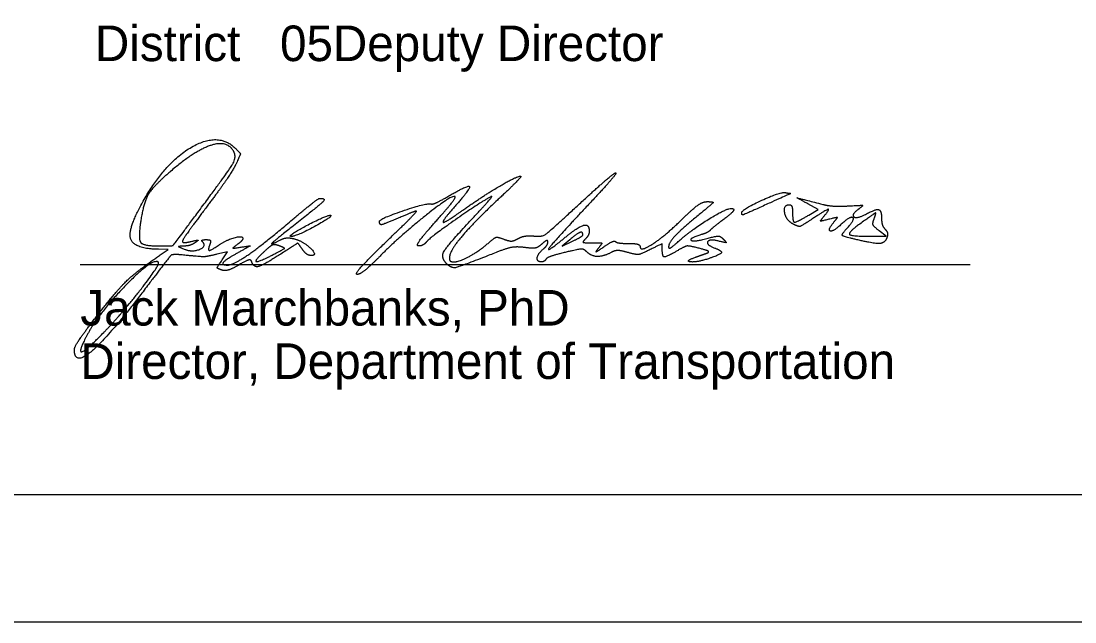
# Model space of a CAD drawing. Extents: x 0 to 40.4, y 0 to 22.
# Drawn here: x 25.71 to 29.855, y 0 to 2.364 of the extents above; entities that cross this region are included whole.
import ezdxf

# ---------------------------------------------------------------- set-up
doc = ezdxf.new("R2010")
doc.units = 0
for name, color, linetype in [('SH_Border', 7, 'Continuous'), ('SH_Cut_Line', 7, 'Continuous'), ('SH_Data', 7, 'Continuous'), ('SH_Text', 7, 'Continuous')]:
    doc.layers.add(name, color=color, linetype=linetype)

msp = doc.modelspace()

# ---------------------------------------------------------------- linework, layer by layer
at = {"layer": 'SH_Border'}
msp.add_lwpolyline([(2, 21.5), (33.5, 21.5), (33.5, 0.5), (2, 0.5)], close=True, dxfattribs=at)
at = {"layer": 'SH_Cut_Line'}
msp.add_lwpolyline([(0, 0), (34, 0), (34, 22), (0, 22)], close=True, dxfattribs=at)
at = {"layer": 'SH_Data'}
msp.add_line((25.9426, 1.4059), (29.4426, 1.4059), dxfattribs=at)
at = {"layer": 'SH_Text'}
for p, q in [((26.4049, 1.6109), (26.4049, 1.6109)), ((28.5442, 1.6101), (28.5442, 1.6101)), ((26.7703, 1.5211), (26.7703, 1.5211)), ((27.9192, 1.5231), (27.9192, 1.5231)), ((28.9967, 1.5038), (28.9967, 1.5038)), ((26.7255, 1.4794), (26.7255, 1.4794)), ((27.1421, 1.492), (27.1421, 1.492))]:
    msp.add_line(p, q, dxfattribs=at)
for points in [[(28.808, 1.6005), (28.8444, 1.622), (28.8037, 1.645)], [(29.0567, 1.517), (29.113, 1.5171), (29.0842, 1.5392)], [(27.8675, 1.5034), (27.838, 1.4778), (27.8786, 1.4975)], [(26.2573, 1.444), (26.288, 1.4652), (26.2501, 1.4659)], [(26.5002, 1.4241), (26.5214, 1.4565), (26.4797, 1.4464)]]:
    msp.add_lwpolyline(points, dxfattribs=at)
for points in [[(26.1936, 1.6617), (26.2799, 1.8121), (26.488, 1.9281), (26.5537, 1.8624)], [(26.5447, 1.8533), (26.5187, 1.8953), (26.3926, 1.8541), (26.2973, 1.7725)], [(26.4049, 1.6109), (26.5263, 1.7744), (26.5587, 1.8306), (26.5447, 1.8533)], [(26.5537, 1.8624), (26.5724, 1.8437), (26.5725, 1.8386), (26.5541, 1.8002)], [(26.5541, 1.8002), (26.5432, 1.7772), (26.4915, 1.7017), (26.4392, 1.6323)], [(26.2973, 1.7725), (26.2306, 1.7154), (26.1918, 1.6513), (26.1807, 1.5801)], [(27.4473, 1.6202), (27.5279, 1.6768), (27.6592, 1.754), (27.6749, 1.754)], [(27.6749, 1.754), (27.6798, 1.754), (27.6385, 1.7114), (27.5831, 1.6593)], [(27.9016, 1.6406), (27.9766, 1.7097), (28.0427, 1.7663), (28.0484, 1.7664)], [(28.0484, 1.7664), (28.0541, 1.7665), (28.0021, 1.7063), (27.9328, 1.6327)], [(27.3884, 1.6737), (27.4671, 1.7198), (27.4794, 1.7066), (27.4201, 1.6393)], [(26.2501, 1.4659), (26.1522, 1.4676), (26.1288, 1.5487), (26.1936, 1.6617)], [(26.7837, 1.5882), (26.8342, 1.6311), (26.8797, 1.6662), (26.8848, 1.6663)], [(26.8848, 1.6663), (26.9097, 1.6668), (26.8863, 1.6413), (26.8005, 1.574)], [(27.4165, 1.6734), (27.4068, 1.6831), (27.1971, 1.5161), (27.1192, 1.4368)], [(27.5567, 1.673), (27.5077, 1.6452), (27.3193, 1.513), (27.3061, 1.497)], [(27.3227, 1.6445), (27.3283, 1.6426), (27.3578, 1.6558), (27.3884, 1.6737)], [(27.3386, 1.5731), (27.3849, 1.6248), (27.4199, 1.6699), (27.4165, 1.6734)], [(27.5831, 1.6593), (27.4835, 1.5656), (27.3942, 1.4574), (27.3942, 1.4305)], [(27.4915, 1.594), (27.5377, 1.6433), (27.567, 1.6788), (27.5567, 1.673)], [(28.5442, 1.6101), (28.5442, 1.6225), (28.697, 1.6928), (28.716, 1.6891)], [(28.716, 1.6891), (28.7366, 1.6851), (28.7374, 1.6855), (28.6158, 1.6308)], [(28.8037, 1.645), (28.7609, 1.6691), (28.7599, 1.6691), (28.863, 1.6427)], [(26.4392, 1.6323), (26.387, 1.5629), (26.3442, 1.5023), (26.3442, 1.4975)], [(27.1194, 1.5759), (27.1196, 1.5864), (27.307, 1.6496), (27.3227, 1.6445)], [(27.4201, 1.6393), (27.3921, 1.6075), (27.3692, 1.5778), (27.3692, 1.5733)], [(27.3692, 1.5733), (27.3692, 1.5689), (27.4044, 1.59), (27.4473, 1.6202)], [(27.7266, 1.5182), (27.7601, 1.5154), (27.7836, 1.5318), (27.9016, 1.6406)], [(27.9328, 1.6327), (27.8032, 1.4952), (27.7711, 1.4479), (27.8533, 1.5156)], [(28.2911, 1.4931), (28.3447, 1.5419), (28.4917, 1.632), (28.5086, 1.6263)], [(28.3099, 1.5843), (28.355, 1.6281), (28.3922, 1.6538), (28.4099, 1.6535)], [(28.4099, 1.6535), (28.4342, 1.653), (28.4303, 1.6466), (28.3817, 1.6066)], [(28.5086, 1.6263), (28.5169, 1.6235), (28.5017, 1.6048), (28.4746, 1.5846)], [(28.6158, 1.6308), (28.5532, 1.6027), (28.5442, 1.6001), (28.5442, 1.6101)], [(28.7452, 1.566), (28.7187, 1.5801), (28.7078, 1.6415), (28.7317, 1.6415)], [(28.7317, 1.6415), (28.7386, 1.6415), (28.7442, 1.6275), (28.7442, 1.6103)], [(28.8676, 1.5957), (28.892, 1.6253), (28.8762, 1.6215), (28.82, 1.5843)], [(28.863, 1.6427), (28.8836, 1.6374), (28.9286, 1.6347), (28.963, 1.6366)], [(28.963, 1.6366), (29.0178, 1.6397), (29.0227, 1.6381), (29.0028, 1.6233)], [(29.0028, 1.6233), (28.974, 1.6018), (28.997, 1.5854), (29.0306, 1.6034)], [(29.0306, 1.6034), (29.0709, 1.625), (29.0942, 1.6192), (29.0942, 1.5878)], [(26.1807, 1.5801), (26.1693, 1.5067), (26.1907, 1.479), (26.2588, 1.479)], [(26.2588, 1.479), (26.3055, 1.479), (26.31, 1.4831), (26.4049, 1.6109)], [(26.5224, 1.404), (26.5455, 1.404), (26.6715, 1.4928), (26.7837, 1.5882)], [(26.7703, 1.5211), (26.7906, 1.5389), (26.9227, 1.6047), (26.9278, 1.5996)], [(26.9278, 1.5996), (26.934, 1.5934), (26.7914, 1.5165), (26.7737, 1.5165)], [(27.2005, 1.5915), (27.1379, 1.5647), (27.1191, 1.5611), (27.1194, 1.5759)], [(27.1421, 1.492), (27.2131, 1.5605), (27.2684, 1.6165), (27.265, 1.6165)], [(27.265, 1.6165), (27.2616, 1.6165), (27.2325, 1.6053), (27.2005, 1.5915)], [(27.3844, 1.4084), (27.3592, 1.4336), (27.3882, 1.4837), (27.4915, 1.594)], [(28.1442, 1.4775), (28.1442, 1.4547), (28.2395, 1.5161), (28.3099, 1.5843)], [(28.3817, 1.6066), (28.3077, 1.5456), (28.2567, 1.4921), (28.2567, 1.4754)], [(28.4746, 1.5846), (28.4476, 1.5644), (28.4227, 1.5444), (28.4192, 1.5401)], [(28.7442, 1.6103), (28.7442, 1.5735), (28.7585, 1.5713), (28.808, 1.6005)], [(28.82, 1.5843), (28.7799, 1.5578), (28.7666, 1.5545), (28.7452, 1.566)], [(28.887, 1.584), (28.8539, 1.5757), (28.8521, 1.5769), (28.8676, 1.5957)], [(28.9071, 1.5733), (28.9217, 1.5908), (28.9194, 1.5921), (28.887, 1.584)], [(28.961, 1.5518), (28.9915, 1.5855), (28.9698, 1.5964), (28.9358, 1.5645)], [(29.0645, 1.5847), (29.0744, 1.6105), (29.0662, 1.6074), (29.0036, 1.5618)], [(29.0842, 1.5392), (29.0639, 1.5549), (29.0581, 1.5681), (29.0645, 1.5847)], [(29.0942, 1.5878), (29.0942, 1.572), (29.1006, 1.5526), (29.1084, 1.5449)], [(26.8005, 1.574), (26.7072, 1.501), (26.6858, 1.4794), (26.7297, 1.5029)], [(27.2728, 1.479), (27.2625, 1.479), (27.2914, 1.5203), (27.3386, 1.5731)], [(27.8533, 1.5156), (27.9017, 1.5555), (27.9442, 1.5659), (27.9442, 1.5378)], [(27.9442, 1.5378), (27.9442, 1.5288), (27.9375, 1.5148), (27.9292, 1.5065)], [(28.4192, 1.5401), (28.4158, 1.5359), (28.4003, 1.5284), (28.3848, 1.5236)], [(28.9358, 1.5645), (28.9039, 1.5345), (28.8808, 1.5416), (28.9071, 1.5733)], [(28.9967, 1.5038), (28.942, 1.5168), (28.9363, 1.5245), (28.961, 1.5518)], [(29.0036, 1.5618), (28.9609, 1.5307), (28.9773, 1.5169), (29.0567, 1.517)], [(29.1084, 1.5449), (29.1162, 1.5371), (29.1192, 1.5219), (29.115, 1.5111)], [(26.3442, 1.4975), (26.3442, 1.4927), (26.3597, 1.4924), (26.3786, 1.4968)], [(26.3546, 1.4657), (26.3845, 1.4538), (26.4407, 1.4783), (26.4233, 1.4958)], [(26.3786, 1.4968), (26.4041, 1.5027), (26.4081, 1.5015), (26.3942, 1.4921)], [(26.4233, 1.4958), (26.4188, 1.5003), (26.425, 1.504), (26.4372, 1.504)], [(26.4372, 1.504), (26.4518, 1.504), (26.4569, 1.4976), (26.4522, 1.4853)], [(26.4883, 1.4834), (26.5172, 1.5032), (26.5817, 1.5207), (26.5817, 1.5088)], [(26.5817, 1.5088), (26.5817, 1.5042), (26.572, 1.4934), (26.5601, 1.4847)], [(26.7297, 1.5029), (26.7423, 1.5097), (26.7662, 1.5118), (26.7828, 1.5076)], [(26.7737, 1.5165), (26.769, 1.5165), (26.7674, 1.5186), (26.7703, 1.5211)], [(26.7828, 1.5076), (26.8189, 1.4984), (26.8773, 1.4415), (26.8506, 1.4415)], [(27.3061, 1.497), (27.2979, 1.4871), (27.2829, 1.479), (27.2728, 1.479)], [(27.4122, 1.4165), (27.434, 1.4165), (27.5153, 1.4617), (27.5517, 1.494)], [(27.5517, 1.494), (27.572, 1.5121), (27.5849, 1.5147), (27.6086, 1.5057)], [(27.6086, 1.5057), (27.6288, 1.498), (27.6476, 1.4987), (27.6636, 1.5077)], [(27.6636, 1.5077), (27.677, 1.5153), (27.7054, 1.52), (27.7266, 1.5182)], [(27.7817, 1.495), (27.7817, 1.5021), (27.7716, 1.4987), (27.7591, 1.4875)], [(27.763, 1.4665), (27.7733, 1.4751), (27.7817, 1.4879), (27.7817, 1.495)], [(27.9192, 1.5231), (27.9192, 1.5366), (27.8951, 1.5274), (27.8675, 1.5034)], [(27.8786, 1.4975), (27.9009, 1.5083), (27.9192, 1.5198), (27.9192, 1.5231)], [(27.9292, 1.5065), (27.9175, 1.4949), (27.9234, 1.4915), (27.9557, 1.4915)], [(28.0019, 1.476), (28.0233, 1.491), (28.044, 1.5001), (28.0479, 1.4961)], [(28.0479, 1.4961), (28.0518, 1.4922), (28.0751, 1.489), (28.0996, 1.489)], [(28.2567, 1.4754), (28.2567, 1.4679), (28.2722, 1.4759), (28.2911, 1.4931)], [(28.3848, 1.5236), (28.3353, 1.5082), (28.3548, 1.4945), (28.4066, 1.5083)], [(28.4066, 1.5083), (28.445, 1.5186), (28.4602, 1.5179), (28.4723, 1.5057)], [(28.4536, 1.4982), (28.4169, 1.5073), (28.4036, 1.4842), (28.438, 1.471)], [(28.4723, 1.5057), (28.485, 1.4928), (28.4814, 1.4914), (28.4536, 1.4982)], [(29.115, 1.5111), (29.1069, 1.49), (29.0658, 1.4875), (28.9967, 1.5038)], [(26.3505, 1.4784), (26.3281, 1.4775), (26.3285, 1.4762), (26.3546, 1.4657)], [(26.3942, 1.4921), (26.3839, 1.4851), (26.3642, 1.479), (26.3505, 1.4784)], [(26.4522, 1.4853), (26.4433, 1.462), (26.4561, 1.4613), (26.4883, 1.4834)], [(26.5669, 1.4547), (26.5158, 1.4265), (26.4961, 1.404), (26.5224, 1.404)], [(26.5601, 1.4847), (26.5412, 1.4709), (26.5432, 1.4696), (26.5757, 1.4745)], [(26.5757, 1.4745), (26.6125, 1.4801), (26.6124, 1.4798), (26.5669, 1.4547)], [(26.6723, 1.4629), (26.6281, 1.4224), (26.6393, 1.4135), (26.6973, 1.4431)], [(26.7255, 1.4794), (26.7082, 1.4858), (26.6917, 1.4806), (26.6723, 1.4629)], [(26.6973, 1.4431), (26.7437, 1.4668), (26.7473, 1.4714), (26.7255, 1.4794)], [(26.8159, 1.4662), (26.799, 1.4903), (26.797, 1.4898), (26.7312, 1.4474)], [(26.8506, 1.4415), (26.841, 1.4415), (26.8254, 1.4526), (26.8159, 1.4662)], [(27.0317, 1.3672), (27.0214, 1.3674), (27.0711, 1.4236), (27.1421, 1.492)], [(27.5841, 1.4559), (27.438, 1.3982), (27.403, 1.3899), (27.3844, 1.4084)], [(27.6896, 1.4731), (27.6604, 1.4768), (27.6206, 1.4703), (27.5841, 1.4559)], [(27.7591, 1.4875), (27.7435, 1.4733), (27.7222, 1.4689), (27.6896, 1.4731)], [(27.756, 1.4165), (27.7376, 1.4165), (27.7422, 1.4493), (27.763, 1.4665)], [(27.8503, 1.454), (27.8119, 1.4448), (27.7777, 1.4326), (27.7741, 1.4269)], [(27.9346, 1.4561), (27.9235, 1.4672), (27.9034, 1.4667), (27.8503, 1.454)], [(28.0309, 1.4536), (28.0002, 1.4371), (27.9523, 1.4384), (27.9346, 1.4561)], [(27.9557, 1.4915), (27.9933, 1.4915), (27.9956, 1.4895), (27.9801, 1.4701)], [(27.9801, 1.4701), (27.9681, 1.4551), (27.9746, 1.4569), (28.0019, 1.476)], [(28.0954, 1.4537), (28.0685, 1.4614), (28.0454, 1.4614), (28.0309, 1.4536)], [(28.1845, 1.465), (28.1471, 1.4465), (28.1286, 1.4442), (28.0954, 1.4537)], [(28.0996, 1.489), (28.1242, 1.489), (28.1442, 1.4838), (28.1442, 1.4775)], [(28.2317, 1.465), (28.2317, 1.4878), (28.2306, 1.4878), (28.1845, 1.465)], [(28.2937, 1.4619), (28.2486, 1.4353), (28.2317, 1.4361), (28.2317, 1.465)], [(28.3768, 1.4699), (28.338, 1.4798), (28.3212, 1.4782), (28.2937, 1.4619)], [(28.4067, 1.4507), (28.4181, 1.4549), (28.4064, 1.4624), (28.3768, 1.4699)], [(28.438, 1.471), (28.4685, 1.4593), (28.4596, 1.4444), (28.4129, 1.429)], [(26.2501, 1.4148), (26.2292, 1.4357), (26.0107, 1.21), (25.9644, 1.1196)], [(26.0063, 1.2018), (26.084, 1.3023), (26.1641, 1.3796), (26.2573, 1.444)], [(26.0345, 1.1384), (26.1021, 1.2075), (26.2578, 1.4071), (26.2501, 1.4148)], [(26.3385, 1.4441), (26.3051, 1.4474), (26.2933, 1.4369), (26.2167, 1.3353)], [(26.4797, 1.4464), (26.4393, 1.4367), (26.417, 1.4363), (26.3385, 1.4441)], [(26.499, 1.3841), (26.4808, 1.3911), (26.4809, 1.3947), (26.5002, 1.4241)], [(26.6167, 1.4177), (26.6139, 1.4263), (26.5947, 1.4211), (26.5656, 1.4039)], [(26.7312, 1.4474), (26.6623, 1.4031), (26.6249, 1.3933), (26.6167, 1.4177)], [(27.1192, 1.4368), (27.0814, 1.3984), (27.042, 1.367), (27.0317, 1.3672)], [(27.3942, 1.4305), (27.3942, 1.4228), (27.4023, 1.4165), (27.4122, 1.4165)], [(27.7741, 1.4269), (27.7706, 1.4212), (27.7624, 1.4165), (27.756, 1.4165)], [(28.4129, 1.429), (28.3663, 1.4136), (28.3189, 1.4193), (28.363, 1.435)], [(28.363, 1.435), (28.3767, 1.4399), (28.3964, 1.447), (28.4067, 1.4507)], [(26.5656, 1.4039), (26.54, 1.3888), (26.51, 1.3799), (26.499, 1.3841)], [(26.2167, 1.3353), (26.0643, 1.1332), (25.9192, 1.0045), (25.9192, 1.0715)], [(25.9192, 1.0715), (25.9192, 1.0812), (25.9584, 1.1398), (26.0063, 1.2018)], [(25.9644, 1.1196), (25.9331, 1.0587), (25.9648, 1.0671), (26.0345, 1.1384)]]:
    msp.add_open_spline(points, degree=2, dxfattribs=at)

# ---------------------------------------------------------------- texts
for s, p in [('District       Deputy Director', (26, 2.2063)), ('              05', (26, 2.2063)), ('Jack Marchbanks, PhD', (25.9426, 1.1659)), ('Director, Department of Transportation', (25.9426, 0.9559))]:
    msp.add_text(s, height=0.14, dxfattribs=at).set_placement(p)

doc.saveas('drawing.dxf')
